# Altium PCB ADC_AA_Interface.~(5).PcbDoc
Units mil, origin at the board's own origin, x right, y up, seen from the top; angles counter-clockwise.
Board outline 2600 x 10000 mil, 6 copper layers (Top Layer, InternalPlane1, MidLayer1, InternalPlane2, InternalPlane3, Bottom Layer); 10 components, 66 nets, 255 pads, 1 vias.
Unrouted connection lines stored in the file: 32.
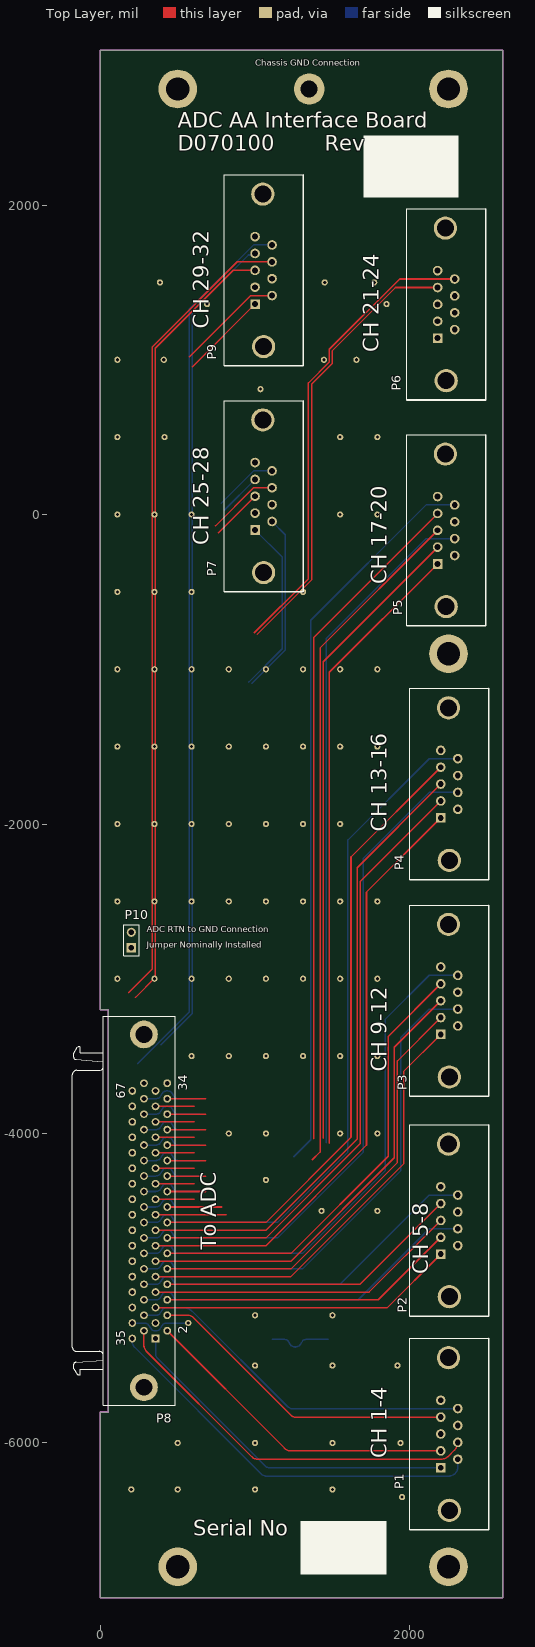
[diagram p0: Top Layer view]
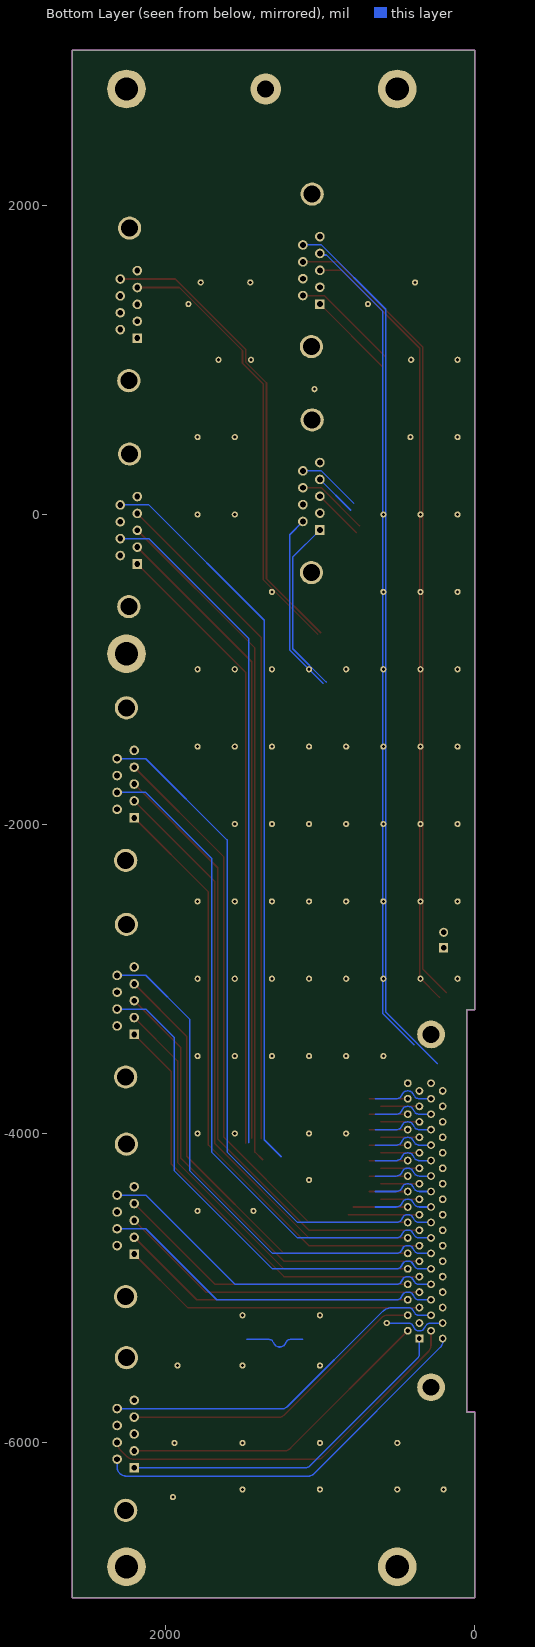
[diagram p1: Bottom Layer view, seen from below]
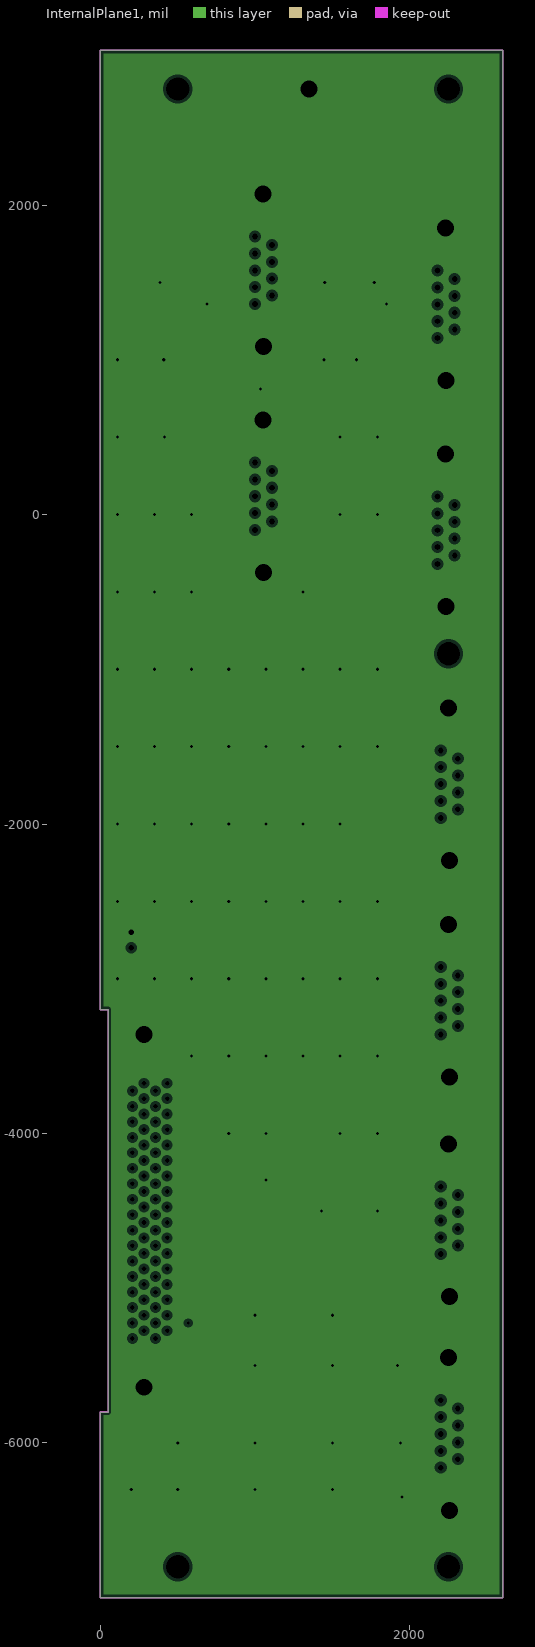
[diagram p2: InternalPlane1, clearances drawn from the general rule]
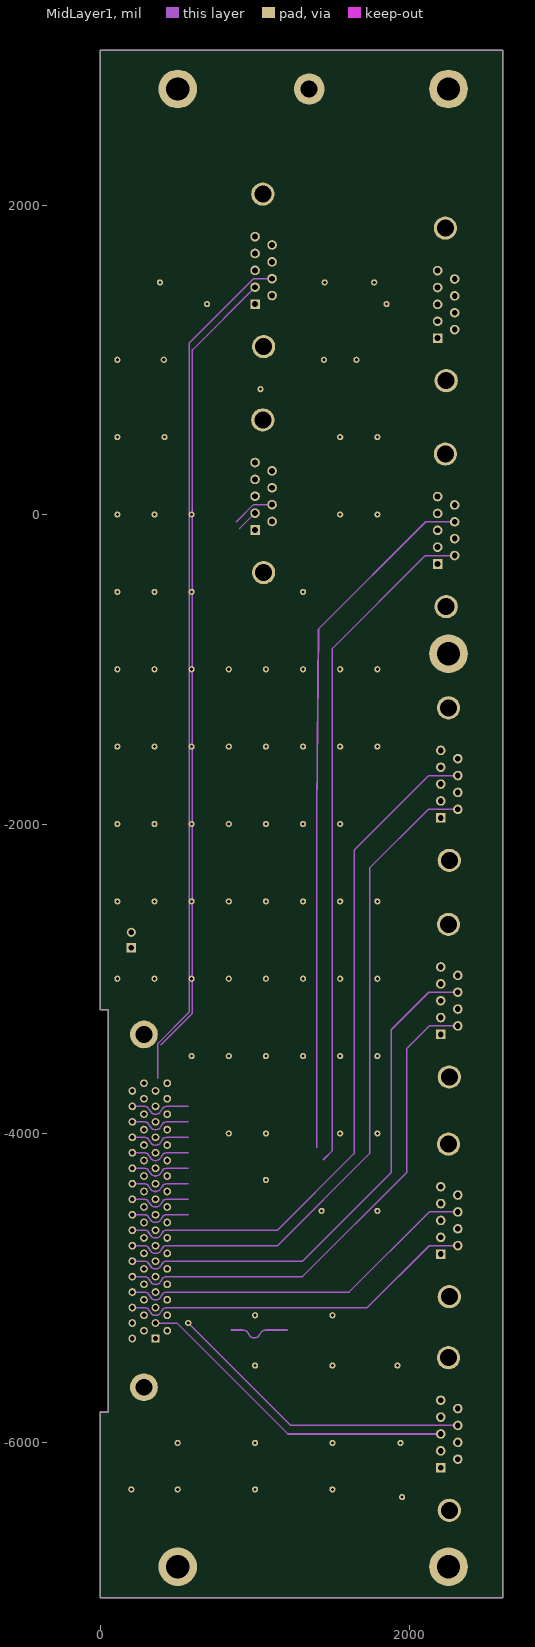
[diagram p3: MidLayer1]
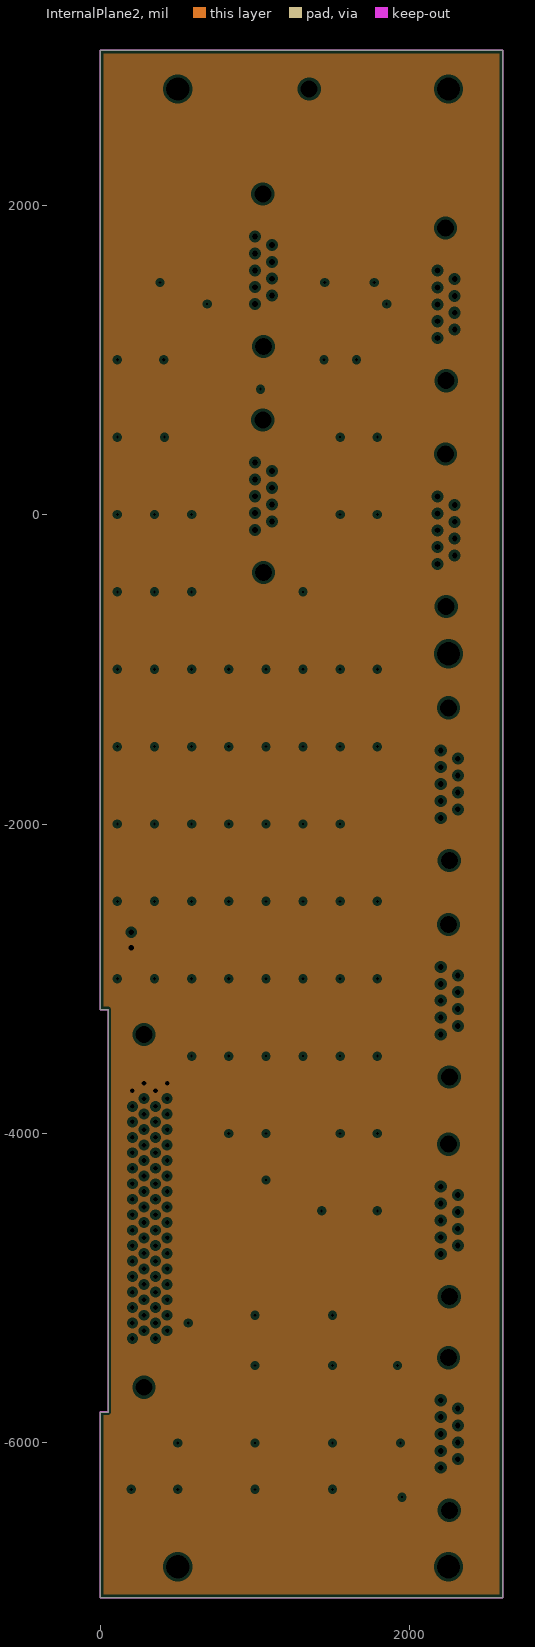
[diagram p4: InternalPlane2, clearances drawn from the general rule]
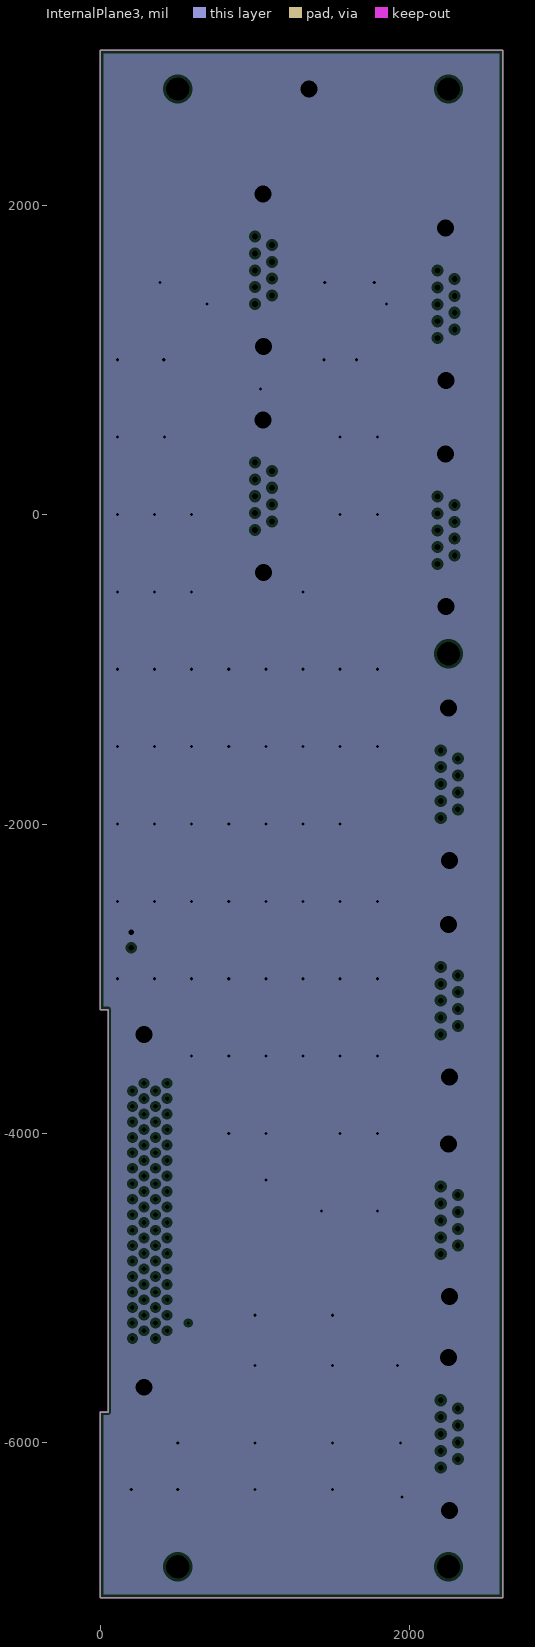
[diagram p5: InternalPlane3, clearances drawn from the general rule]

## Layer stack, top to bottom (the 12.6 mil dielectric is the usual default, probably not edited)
Top Solder: solder mask 0.4, Solder Resist, Dk 3.5
Top Layer: signal copper 1.4
Dielectric1: core 12.6, FR-4, Dk 4.8
InternalPlane1: plane copper 1.4, net GND
Dielectric3: prepreg 12.6, FR-4, Dk 4.8
MidLayer1: signal copper 1.4
Dielectric2: core 12.6, FR-4, Dk 4.8
InternalPlane2: plane copper 1.4, net RTN
Dielectric4: prepreg 12.6, FR-4, Dk 4.8
InternalPlane3: plane copper 1.4, net GND
Dielectric5: core 12.6, FR-4, Dk 4.8
Bottom Layer: signal copper 1.4
Bottom Solder: solder mask 0.4, Solder Resist, Dk 3.5

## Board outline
0,-7000 0,-5800 50,-5800 50,-3200 0,-3200 0,3000 2600,3000 2600,-7000

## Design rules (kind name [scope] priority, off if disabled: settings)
Clearance [All] p1: gap=10 ignorepadtopadclearanceinfootprint=FALSE except(0: Arc-Hole Track-Hole SMDPad-Hole THPad-Hole Via-Hole Fill-Hole Poly-Hole Region-Hole Text-Hole)
FabricationTestPointUsage TestPointUsage [All] p1: valid=0 allowmultiple=FALSE
FabricationTestpoint Testpoint [All] p1: side=3 testpointundercomponent=TRUE minsize=40 maxsize=100 preferedsize=60 minholesize=0 maxholesize=40 preferedholesize=32 testpointgrid=1 allowsidetop=TRUE allowsidebottom=TRUE usegrid=TRUE gridtolerance=0.01
HoleSize [All] p1: absolutevalues=TRUE maxlimit=200 minlimit=1 maxpercent=80.000 minpercent=20.000
PlaneClearance [All] p1: clearance=20
PlaneConnect [All] p1: planeconnectstyle=Relief reliefexpansion=20 reliefentries=4 reliefconductorwidth=10 reliefairgap=10
PolygonConnect [All] p1: connectstyle=Relief reliefconductorwidth=10 reliefentries=4 polygonreliefangle="90 Angle" airgapwidth=10
RoutingVias [All] p1: holewidth=20 width=40 viastyle="Through Hole" minholewidth=20 minwidth=40 maxholewidth=28 maxwidth=50
SolderMaskExpansion [All] p1: expansion=4
Width [All] p1: maxlimit=100 minlimit=10 preferedwidth=10
25 further rules are at their usual default settings.

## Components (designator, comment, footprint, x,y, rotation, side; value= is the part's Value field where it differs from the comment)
P1 "5747871-8" DB9/M 2200,-6160 r270 top
P2 "5747871-8" DB9/M 2200,-4780 r270 top
P3 "5747871-8" DB9/M 2200,-3360 r270 top
P4 "5747871-8" DB9/M 2200,-1960 r270 top
P5 "5747871-8" DB9/M 2180,-320 r270 top
P6 "5747871-8" DB9/M 2180,1140 r270 top
P7 "5747871-8" DB9/M 1000,-100 r270 top
P8 "787082-7" 787082-7 20,-4500 r90 top
P9 "5747871-8" DB9/M 1000,1360 r270 top
P10 "Header 2" HDR1X2 200,-2800 r90 top

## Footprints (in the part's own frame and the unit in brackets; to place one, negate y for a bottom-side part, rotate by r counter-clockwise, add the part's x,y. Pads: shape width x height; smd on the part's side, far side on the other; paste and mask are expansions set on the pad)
787082-7 [mm] "Connector; D Subminiature 050 Series; 68 Position; Right Angle"
  rect 1.27x1.27 hole 0.762: 1(-20.955,-8.555)
  round 1.27 hole 0.762: 2(-19.685,-10.46) 3(-18.415,-8.555) 4(-17.145,-10.46) 5(-15.875,-8.555) 6(-14.605,-10.46) 7(-13.335,-8.555) 8(-12.065,-10.46) 9(-10.795,-8.555) 10(-9.525,-10.46) 11(-8.255,-8.555) 12(-6.985,-10.46) 13(-5.715,-8.555) 14(-4.445,-10.46) 15(-3.175,-8.555) 16(-1.905,-10.46) 17(-0.635,-8.555) 18(0.635,-10.46) 19(1.905,-8.555) 20(3.175,-10.46) 21(4.445,-8.555) 22(5.715,-10.46) 23(6.985,-8.555) 24(8.255,-10.46) 25(9.525,-8.555) 26(10.795,-10.46) 27(12.065,-8.555) 28(13.335,-10.46) 29(14.605,-8.555) 30(15.875,-10.46) 31(17.145,-8.555) 32(18.415,-10.46) 33(19.685,-8.555) 34(20.955,-10.46) 35(-20.955,-4.745) 36(-19.685,-6.65) 37(-18.415,-4.745) 38(-17.145,-6.65) 39(-15.875,-4.745) 40(-14.605,-6.65) 41(-13.335,-4.745) 42(-12.065,-6.65) 43(-10.795,-4.745) 44(-9.525,-6.65) 45(-8.255,-4.745) 46(-6.985,-6.65) 47(-5.715,-4.745) 48(-4.445,-6.65) 49(-3.175,-4.745) 50(-1.905,-6.65) 51(-0.635,-4.745) 52(0.635,-6.65) 53(1.905,-4.745) 54(3.175,-6.65) 55(4.445,-4.745) 56(5.715,-6.65) 57(6.985,-4.745) 58(8.255,-6.65) 59(9.525,-4.745) 60(10.795,-6.65) 61(12.065,-4.745) 62(13.335,-6.65) 63(14.605,-4.745) 64(15.875,-6.65) 65(17.145,-4.745) 66(18.415,-6.65) 67(19.685,-4.745) 68(20.955,-6.65)
  round 4.55 hole 2.77: 69(-28.955,-6.65) 70(28.955,-6.65)
  silkscreen extent -31.95,-11.76 31.95,5.11
DB9/M [mil]
  round 150 hole 110: 0(-711,50) 0(275,55)
  rect 62x62 hole 38: 1(0,0)
  round 62 hole 38: 2(-109,0) 3(-218,0) 4(-327,0) 5(-436,0) 6(-55,110) 7(-164,110) 8(-273,110) 9(-382,110)
  silkscreen extent -836,-200 400,310
HDR1X2 [mm] "Connector; Header; 2 Position"
  rect 1.5x1.5 hole 0.9: 1(0,0)
  round 1.5 hole 0.9: 2(2.54,0)
  silkscreen extent -1.27,-1.27 3.81,1.27

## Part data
P1 P2 P3 P4 P5 P6 P7 P9: library part 788754-1, "Plug Assembly, Size 1, 9 Position, Right Angle, 8.08mm Series, Amplimite"
P8: library part "PE50E-080 Connector", "3M Pak 50 plug connector"
P10: "Header, 2-Pin"

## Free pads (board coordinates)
  round 40 hole 20: 0(500,-6000) 1(1000,-6000) 2(1500,-6000) 3(1940,-6000) 4(1000,-5500) 5(1500,-5500) 6(1920,-5500) 9(1790,-4500) 10(1000,-5175) 11(1500,-5175) 16(1790,-4000) 17(1790,-3500) 20(1070,-4300) 20(1430,-4500) 22(1550,-4000) 23(1550,-3500) 24(1550,-3000) 31(1310,-3000) 32(1310,-3500) 33(1790,-3000) 37(830,-4000) 38(830,-3500) 39(830,-3000) 40(830,-2500) 41(350,-2500) 42(590,-2500) 43(350,-3000) 44(590,-3000) 45(1070,-2500) 46(1790,-2500) 47(1310,-2500) 48(1550,-2500) 50(590,-3500) 52(1070,-4000) 53(1070,-3500) 54(1070,-3000) 55(350,-2000) 56(590,-2000) 57(830,-2000) 58(1070,-2000) 60(1310,-2000) 61(1550,-2000) 62(1550,-1500) 63(1310,-1500) 64(1790,-1500) 64(1790,-1000) 65(1070,-1500) 66(830,-1500) 67(590,-1500) 68(350,-1500) 69(350,-1000) 70(590,-1000) 71(830,-1000) 72(1070,-1000) 73(1310,-1000) 74(1550,-1000) 76(110,1000) 77(110,500) 78(110,0) 78(350,-500) 79(110,-500) 79(590,-500) 80(110,-1000) 81(110,-1500) 82(110,-2000) 82(1310,-500) 83(110,-2500) 83(350,0) 84(110,-3000) 84(590,0) 85(200,-6300) 85(1790,0) 86(500,-6300) 86(1550,0) 87(1000,-6300) 87(1550,500) 88(415,500) 88(1500,-6300) 89(410,1000) 89(1950,-6350) 90(1035,810) 91(1445,1000) 92(1655,1000) 93(1790,500) 94(1450,1500) 95(1770,1500) 96(385,1500) 97(690,1360) 98(1850,1360)
  round 200 hole 110: 0(1350,2750)
  round 250 hole 150: 0(2250,-6800) 1(2250,2750) 2(500,2750) 3(500,-6800) 4(2250,-900)

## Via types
v1: diameter 40, hole 20, Top Layer to Bottom Layer, 1 vias

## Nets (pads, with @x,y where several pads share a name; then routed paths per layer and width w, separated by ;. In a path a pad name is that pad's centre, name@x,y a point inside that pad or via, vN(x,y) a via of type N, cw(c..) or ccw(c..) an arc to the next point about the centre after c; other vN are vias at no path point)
GND: P1.0 P2.0 P3.0 P4.0 P5.0 P6.0 P7.0 P8.69 P8.70 P9.0 P10.2 pad.0@500,-6000 pad.0@1350,2750 pad.1@1000,-6000 pad.2@1500,-6000 pad.3@1940,-6000 pad.4@1000,-5500 pad.5 pad.6 pad.9 pad.10 pad.11 pad.16 pad.17 pad.20 pad.22 pad.23 pad.24 pad.31 pad.32 pad.33 pad.37 pad.38 pad.39 pad.40 pad.41 pad.42 pad.43 pad.44 pad.45 pad.46 pad.47 pad.48 pad.50 pad.52 pad.53 pad.54 pad.55 pad.56 pad.57 pad.58 pad.60 pad.61 pad.62 pad.63 pad.64 pad.65 pad.66 pad.67 pad.68 pad.69 pad.70 pad.71 pad.72 pad.73 pad.74 pad.76 pad.77 pad.78 pad.79 pad.80 pad.81 pad.82 pad.83 pad.84 pad.85 pad.86 pad.87 pad.88 pad.89 pad.90 pad.91 pad.92 pad.93 pad.94 pad.95 pad.96 pad.97 pad.98
OUTPUTN1: P1.6 P8.35 | length 2576
  Bottom Layer w10: P8.35 206.81,-5348.16 ccw(c251.84,-5348.16) 220,-5380 1040,-6200 ccw(c1073.8,-6166.2) 1073.8,-6214 2251.92,-6214 ccw(c2251.92,-6155.87) 2293.03,-6196.97 ccw(c2251.96,-6155.96) 2310,-6155.96 P1.6
OUTPUTN2: P1.7 P8.36 | length 2523.7
  Top Layer w10: P8.36 281.81,-5370 ccw(c334.47,-5370) 297.23,-5407.23 ; 300,-5410 297.23,-5407.23 ; 1020,-6105 1016.21,-6105 ; P1.7@2310,-6020 P1.7 cw(c2239.99,-5996) 2289.49,-6045.51 2251.21,-6083.79 cw(c2200,-6032.57) 2200,-6105 1016.21,-6105 ; 297.23,-5407.23 980.03,-6090.03 ccw(c1016.21,-6053.79) 1016.21,-6105
OUTPUTN3: P1.8 P8.37 | length 2419.6
  MidLayer1 w10: v1(568.12,-5225) 1230.12,-5887 P1.8
  Bottom Layer w10: P8.37 280,-5225 ; 281.81,-5225 cw(c281.81,-5275) 307.3,-5231.99 ; 406.18,-5232.07 382.54,-5267.87 cw(c356.81,-5225) 331.08,-5267.87 307.44,-5232.07 ; 406.32,-5231.99 cw(c431.81,-5275) 431.81,-5225 v1(568.12,-5225) ; 307.3,-5231.99 cw(c281.81,-5275) 307.44,-5232.07 ; 307.3,-5231.99 cw(c356.81,-5225) 307.28,-5231.82 307.44,-5232.07
OUTPUTN4: P1.9 P8.38 | length 2322.5
  Bottom Layer w10: P8.38 355,-5175 ; 356.81,-5175 ccw(c356.81,-5125) 382.3,-5168.01 ; 382.44,-5167.93 406.08,-5132.13 cw(c431.81,-5175) 431.81,-5125 528.58,-5125 cw(c528.58,-5225) 599.29,-5154.29 1210.98,-5765.98 ccw(c1240,-5736.96) 1240,-5778 ; 1230,-5778 1240,-5778 ; P1.9 1240,-5778
OUTPUTN5: P2.6 P8.39 | length 2311
  MidLayer1 w10: P8.39 280,-5125 ; 281.81,-5125 cw(c281.81,-5175) 307.3,-5131.99 ; 406.18,-5132.07 382.54,-5167.87 cw(c356.81,-5125) 356.81,-5175 cw(c356.81,-5125) 331.08,-5167.87 307.44,-5132.07 ; 406.32,-5131.99 cw(c431.81,-5175) 431.81,-5125 1725,-5125 2125,-4725 P2.6 ; 307.3,-5131.99 cw(c356.81,-5125) 307.28,-5131.82 307.44,-5132.07 ; 307.3,-5131.99 cw(c281.81,-5175) 307.44,-5132.07
OUTPUTN6: P2.7 P8.40 | length 2260.5
  Bottom Layer w10: P8.40 355,-5075 ; 356.81,-5075 ccw(c356.81,-5025) 382.3,-5068.01 ; 481.18,-5067.93 457.54,-5032.13 ccw(c431.81,-5075) 431.81,-5025 ccw(c431.81,-5075) 406.08,-5032.13 382.44,-5067.93 ; 481.32,-5068.01 ccw(c506.81,-5025) 506.81,-5075 1666,-5075 2125,-4616 P2.7 ; 382.3,-5068.01 ccw(c356.81,-5025) 382.44,-5067.93 ; 382.3,-5068.01 ccw(c431.81,-5075) 382.28,-5068.18 382.44,-5067.93
OUTPUTN7: P2.8 P8.41 | length 2359.9
  MidLayer1 w10: P8.41 280,-5025 ; 281.81,-5025 cw(c281.81,-5075) 307.3,-5031.99 ; 406.18,-5032.07 382.54,-5067.87 cw(c356.81,-5025) 356.81,-5075 cw(c356.81,-5025) 331.08,-5067.87 307.44,-5032.07 ; 406.32,-5031.99 cw(c431.81,-5075) 431.81,-5025 1607,-5025 2125,-4507 P2.8 ; 307.3,-5031.99 cw(c356.81,-5025) 307.28,-5031.82 307.44,-5032.07 ; 307.3,-5031.99 cw(c281.81,-5075) 307.44,-5032.07
OUTPUTN8: P2.9 P8.42 | length 2309.4
  Bottom Layer w10: P8.42 355,-4975 ; 356.81,-4975 ccw(c356.81,-4925) 382.3,-4968.01 ; 481.18,-4967.93 457.54,-4932.13 ccw(c431.81,-4975) 406.08,-4932.13 382.44,-4967.93 ; 481.32,-4968.01 ccw(c506.81,-4925) 506.81,-4975 1548,-4975 2125,-4398 P2.9 ; 382.3,-4968.01 ccw(c431.81,-4975) 382.28,-4968.18 382.44,-4967.93 ; 382.3,-4968.01 ccw(c356.81,-4925) 382.44,-4967.93
OUTPUTN9: P3.6 P8.43 | length 3286.1
  MidLayer1 w10: P8.43 280,-4925 ; 281.81,-4925 cw(c281.81,-4975) 307.3,-4931.99 ; 406.18,-4932.07 382.54,-4967.87 cw(c356.81,-4925) 356.81,-4975 cw(c356.81,-4925) 331.08,-4967.87 307.44,-4932.07 ; 406.32,-4931.99 cw(c431.81,-4975) 431.81,-4925 1306.81,-4925 1980,-4251.81 1980,-3450 2125,-3305 P3.6 ; 307.3,-4931.99 cw(c356.81,-4925) 307.28,-4931.82 307.44,-4932.07 ; 307.3,-4931.99 cw(c281.81,-4975) 307.44,-4932.07
OUTPUTN10: P3.7 P8.44 | length 3270.1
  Bottom Layer w10: P8.44 355,-4875 ; 356.81,-4875 ccw(c356.81,-4825) 382.3,-4868.01 ; 481.18,-4867.93 457.54,-4832.13 ccw(c431.81,-4875) 431.81,-4825 ccw(c431.81,-4875) 406.08,-4832.13 382.44,-4867.93 ; 481.32,-4868.01 ccw(c506.81,-4825) 506.81,-4875 1306.81,-4875 1940,-4241.81 1940,-3381 2125,-3196 P3.7 ; 382.3,-4868.01 ccw(c356.81,-4825) 382.44,-4867.93 ; 382.3,-4868.01 ccw(c431.81,-4875) 382.28,-4868.18 382.44,-4867.93
OUTPUTN11: P3.8 P8.45 | length 3405.2
  MidLayer1 w10: P8.45 280,-4825 ; 281.81,-4825 cw(c281.81,-4875) 307.3,-4831.99 ; 406.18,-4832.07 382.54,-4867.87 cw(c356.81,-4825) 356.81,-4875 cw(c356.81,-4825) 331.08,-4867.87 307.44,-4832.07 ; 406.32,-4831.99 cw(c431.81,-4875) 431.81,-4825 1306.81,-4825 1880,-4251.81 1880,-3330 2123,-3087 P3.8 ; 307.3,-4831.99 cw(c356.81,-4825) 307.28,-4831.82 307.44,-4832.07 ; 307.3,-4831.99 cw(c281.81,-4875) 307.44,-4832.07
OUTPUTN12: P3.9 P8.46 | length 3388.1
  Bottom Layer w10: P8.46 355,-4775 ; 356.81,-4775 ccw(c356.81,-4725) 382.3,-4768.01 ; 481.18,-4767.93 457.54,-4732.13 ccw(c431.81,-4775) 431.81,-4725 ccw(c431.81,-4775) 406.08,-4732.13 382.44,-4767.93 ; 481.32,-4768.01 ccw(c506.81,-4725) 506.81,-4775 1306.81,-4775 1840,-4241.81 1840,-3263 2125,-2978 P3.9 ; 382.3,-4768.01 ccw(c356.81,-4725) 382.44,-4767.93 ; 382.3,-4768.01 ccw(c431.81,-4775) 382.28,-4768.18 382.44,-4767.93
OUTPUTN13: P4.6 P8.47 | length 5232.7
  MidLayer1 w10: P8.47 280,-4725 ; 281.81,-4725 cw(c281.81,-4775) 307.3,-4731.99 ; 406.18,-4732.07 382.54,-4767.87 cw(c356.81,-4725) 356.81,-4775 cw(c356.81,-4725) 331.08,-4767.87 307.44,-4732.07 ; 406.32,-4731.99 cw(c431.81,-4775) 431.81,-4725 1145,-4725 ; 2120,-1905 1740,-2285 1740,-4130 ; 2123,-1905 P4.6 ; 307.3,-4731.99 cw(c356.81,-4725) 307.28,-4731.82 307.44,-4732.07 ; 307.3,-4731.99 cw(c281.81,-4775) 307.44,-4732.07 ; 1145,-4725 1740,-4130 ; 1145,-4725 1740,-4130
OUTPUTN14: P4.7 P8.48 | length 4375.3
  Bottom Layer w10: P8.48 355,-4675 ; 356.81,-4675 ccw(c356.81,-4625) 382.3,-4668.01 ; 481.18,-4667.93 457.54,-4632.13 ccw(c431.81,-4675) 431.81,-4625 ccw(c431.81,-4675) 406.08,-4632.13 382.44,-4667.93 ; 481.32,-4668.01 ccw(c506.81,-4625) 506.81,-4675 1145,-4675 1700,-4120 1700,-2221 2125,-1796 P4.7 ; 382.3,-4668.01 ccw(c356.81,-4625) 382.44,-4667.93 ; 382.3,-4668.01 ccw(c431.81,-4675) 382.28,-4668.18 382.44,-4667.93
OUTPUTN15: P4.8 P8.49 | length 4510.5
  MidLayer1 w10: P8.49 280,-4625 ; 281.81,-4625 cw(c281.81,-4675) 307.3,-4631.99 ; 406.18,-4632.07 382.54,-4667.87 cw(c356.81,-4625) 356.81,-4675 cw(c356.81,-4625) 331.08,-4667.87 307.44,-4632.07 ; 406.32,-4631.99 cw(c431.81,-4675) 431.81,-4625 1145,-4625 1640,-4130 1640,-2170 2123,-1687 P4.8 ; 307.3,-4631.99 cw(c356.81,-4625) 307.28,-4631.82 307.44,-4632.07 ; 307.3,-4631.99 cw(c281.81,-4675) 307.44,-4632.07
OUTPUTN16: P4.9 P8.50 | length 4493.3
  Bottom Layer w10: P8.50 355,-4575 ; 356.81,-4575 ccw(c356.81,-4525) 382.3,-4568.01 ; 481.18,-4567.93 457.54,-4532.13 ccw(c431.81,-4575) 431.81,-4525 ccw(c431.81,-4575) 406.08,-4532.13 382.44,-4567.93 ; 481.32,-4568.01 ccw(c506.81,-4525) 506.81,-4575 1145,-4575 1600,-4120 1600,-2103 2125,-1578 P4.9 ; 382.3,-4568.01 ccw(c356.81,-4525) 382.44,-4567.93 ; 382.3,-4568.01 ccw(c431.81,-4575) 382.28,-4568.18 382.44,-4567.93
OUTPUTN17: P5.6 P8.51 | length 4768.9
  MidLayer1 w10: P8.51 280,-4525 ; 281.81,-4525 cw(c281.81,-4575) 307.3,-4531.99 ; 406.18,-4532.07 382.54,-4567.87 cw(c356.81,-4525) 356.81,-4575 cw(c356.81,-4525) 331.08,-4567.87 307.44,-4532.07 ; 406.32,-4531.99 cw(c431.81,-4575) 431.81,-4525 568.12,-4525 ; 1440,-4170 1500,-4110 1500,-865 2100,-265 ; 2103,-265 P5.6 ; 307.3,-4531.99 cw(c356.81,-4525) 307.28,-4531.82 307.44,-4532.07 ; 307.3,-4531.99 cw(c281.81,-4575) 307.44,-4532.07
OUTPUTN18: P5.7 P8.52 | length 4759.6
  Bottom Layer w10: P8.52 355,-4475 ; 356.81,-4475 ccw(c356.81,-4425) 382.3,-4468.01 ; 481.18,-4467.93 457.54,-4432.13 ccw(c431.81,-4475) 431.81,-4425 ccw(c431.81,-4475) 406.08,-4432.13 382.44,-4467.93 ; 481.32,-4468.01 ccw(c506.81,-4425) 506.81,-4475 643.12,-4475 ; 1460,-4060 1460,-801 2105,-156 P5.7 ; 382.3,-4468.01 ccw(c356.81,-4425) 382.44,-4467.93 ; 382.3,-4468.01 ccw(c431.81,-4475) 382.28,-4468.18 382.44,-4467.93
OUTPUTN19: P5.8 P8.53 | length 4922.2
  MidLayer1 w10: P8.53 280,-4425 ; 281.81,-4425 cw(c281.81,-4475) 307.3,-4431.99 ; 406.18,-4432.07 382.54,-4467.87 cw(c356.81,-4425) 356.81,-4475 cw(c356.81,-4425) 331.08,-4467.87 307.44,-4432.07 ; 406.32,-4431.99 cw(c431.81,-4475) 431.81,-4425 568.12,-4425 ; 1400,-4091.63 1400,-1932.13 1410,-740 2103,-47 P5.8 ; 307.3,-4431.99 cw(c356.81,-4425) 307.28,-4431.82 307.44,-4432.07 ; 307.3,-4431.99 cw(c281.81,-4475) 307.44,-4432.07
OUTPUTN20: P5.9 P8.54 | length 5154.6
  Bottom Layer w10: P8.54 355,-4375 ; 356.81,-4375 ccw(c356.81,-4325) 382.3,-4368.01 ; 481.18,-4367.93 457.54,-4332.13 ccw(c431.81,-4375) 431.81,-4325 ccw(c431.81,-4375) 406.08,-4332.13 382.44,-4367.93 ; 481.32,-4368.01 ccw(c506.81,-4325) 506.81,-4375 643.12,-4375 ; 1250,-4150 1360,-4040 1360,-683 2105,62 P5.9 ; 382.3,-4368.01 ccw(c356.81,-4325) 382.44,-4367.93 ; 382.3,-4368.01 ccw(c431.81,-4375) 382.28,-4368.18 382.44,-4367.93
OUTPUTN21: P6.6 P8.55 | length 403.5
  MidLayer1 w10: P8.55 280,-4325 ; 281.81,-4325 cw(c281.81,-4375) 307.3,-4331.99 ; 406.18,-4332.07 382.54,-4367.87 cw(c356.81,-4325) 331.08,-4367.87 307.44,-4332.07 ; 406.32,-4331.99 cw(c431.81,-4375) 431.81,-4325 568.12,-4325 ; 307.3,-4331.99 cw(c356.81,-4325) 307.28,-4331.82 307.44,-4332.07 ; 307.3,-4331.99 cw(c281.81,-4375) 307.44,-4332.07
OUTPUTN22: P6.7 P8.56 | length 403.5
  Bottom Layer w10: P8.56 355,-4275 ; 356.81,-4275 ccw(c356.81,-4225) 382.3,-4268.01 ; 481.18,-4267.93 457.54,-4232.13 ccw(c431.81,-4275) 406.08,-4232.13 382.44,-4267.93 ; 481.32,-4268.01 ccw(c506.81,-4225) 506.81,-4275 643.12,-4275 ; 382.3,-4268.01 ccw(c356.81,-4225) 382.44,-4267.93 ; 382.3,-4268.01 ccw(c431.81,-4275) 382.28,-4268.18 382.44,-4267.93
OUTPUTN23: P6.8 P8.57 | length 403.5
  MidLayer1 w10: P8.57 280,-4225 ; 281.81,-4225 cw(c281.81,-4275) 307.3,-4231.99 ; 406.18,-4232.07 382.54,-4267.87 cw(c356.81,-4225) 331.08,-4267.87 307.44,-4232.07 ; 406.32,-4231.99 cw(c431.81,-4275) 431.81,-4225 568.12,-4225 ; 307.3,-4231.99 cw(c356.81,-4225) 307.28,-4231.82 307.44,-4232.07 ; 307.3,-4231.99 cw(c281.81,-4275) 307.44,-4232.07
OUTPUTN24: P6.9 P8.58 | length 3434.8
  Top Layer w10: 995,-764.5 1345,-414.5 1345,850.5 1480,985.5 1480,1067.78 1934.22,1522 P6.9
  Bottom Layer w10: P8.58 355,-4175 ; 356.81,-4175 ccw(c356.81,-4125) 382.3,-4168.01 ; 481.18,-4167.93 457.54,-4132.13 ccw(c431.81,-4175) 406.08,-4132.13 382.44,-4167.93 ; 481.32,-4168.01 ccw(c506.81,-4125) 506.81,-4175 643.12,-4175 ; 382.3,-4168.01 ccw(c356.81,-4125) 382.44,-4167.93 ; 382.3,-4168.01 ccw(c431.81,-4175) 382.28,-4168.18 382.44,-4167.93
OUTPUTN25: P7.6 P8.59 | length 1573.2
  MidLayer1 w10: P8.59 280,-4125 ; 281.81,-4125 cw(c281.81,-4175) 307.3,-4131.99 ; 406.18,-4132.07 382.54,-4167.87 cw(c356.81,-4125) 331.08,-4167.87 307.44,-4132.07 ; 406.32,-4131.99 cw(c431.81,-4175) 431.81,-4125 568.12,-4125 ; 307.3,-4131.99 cw(c356.81,-4125) 307.28,-4131.82 307.44,-4132.07 ; 307.3,-4131.99 cw(c281.81,-4175) 307.44,-4132.07
  Bottom Layer w10: 980,-1090.5 1195,-875.5 1195,-130 P7.6
OUTPUTN26: P7.7 P8.60 | length 679
  MidLayer1 w10: 880,-45.95 989.95,64 P7.7
  Bottom Layer w10: P8.60 355,-4075 ; 356.81,-4075 ccw(c356.81,-4025) 382.3,-4068.01 ; 481.18,-4067.93 457.54,-4032.13 ccw(c431.81,-4075) 406.08,-4032.13 382.44,-4067.93 ; 481.32,-4068.01 ccw(c506.81,-4025) 506.81,-4075 643.12,-4075 ; 382.3,-4068.01 ccw(c356.81,-4025) 382.44,-4067.93 ; 382.3,-4068.01 ccw(c431.81,-4075) 382.28,-4068.18 382.44,-4067.93
OUTPUTN27: P7.8 P8.61 | length 871.9
  Top Layer w10: 743.6,-73.35 989.95,173 P7.8
  MidLayer1 w10: P8.61 280,-4025 ; 281.81,-4025 cw(c281.81,-4075) 307.3,-4031.99 ; 406.18,-4032.07 382.54,-4067.87 cw(c356.81,-4025) 331.08,-4067.87 307.44,-4032.07 ; 406.32,-4031.99 cw(c431.81,-4075) 431.81,-4025 568.12,-4025 ; 307.3,-4031.99 cw(c356.81,-4025) 307.28,-4031.82 307.44,-4032.07 ; 307.3,-4031.99 cw(c281.81,-4075) 307.44,-4032.07
OUTPUTN28: P7.9 P8.62 | length 820.4
  Bottom Layer w10: P8.62 355,-3975 ; 356.81,-3975 ccw(c356.81,-3925) 382.3,-3968.01 ; 481.18,-3967.93 457.54,-3932.13 ccw(c431.81,-3975) 406.08,-3932.13 382.44,-3967.93 ; 481.32,-3968.01 ccw(c506.81,-3925) 506.81,-3975 643.12,-3975 ; 780,72.05 989.95,282 P7.9 ; 382.3,-3968.01 ccw(c356.81,-3925) 382.44,-3967.93 ; 382.3,-3968.01 ccw(c431.81,-3975) 382.28,-3968.18 382.44,-3967.93
OUTPUTN29: P8.63 P9.6 | length 1102.8
  Top Layer w10: 575,1018.21 971.79,1415 P9.6
  MidLayer1 w10: P8.63 280,-3925 ; 281.81,-3925 cw(c281.81,-3975) 307.3,-3931.99 ; 406.18,-3932.07 382.54,-3967.87 cw(c356.81,-3925) 331.08,-3967.87 307.44,-3932.07 ; 406.32,-3931.99 cw(c431.81,-3975) 431.81,-3925 568.12,-3925 ; 307.3,-3931.99 cw(c356.81,-3925) 307.28,-3931.82 307.44,-3932.07 ; 307.3,-3931.99 cw(c281.81,-3975) 307.44,-3932.07
OUTPUTN30: P8.64 P9.7 | length 5945.1
  MidLayer1 w10: 371.81,-3641.57 371.81,-3417.92 575,-3214.73 575,1109.05 989.95,1524 P9.7
  Bottom Layer w10: P8.64 355,-3875 ; 356.81,-3875 ccw(c356.81,-3825) 382.3,-3868.01 ; 481.18,-3867.93 457.54,-3832.13 ccw(c431.81,-3875) 406.08,-3832.13 382.44,-3867.93 ; 481.32,-3868.01 ccw(c506.81,-3825) 506.81,-3875 643.12,-3875 ; 382.3,-3868.01 ccw(c356.81,-3825) 382.44,-3867.93 ; 382.3,-3868.01 ccw(c431.81,-3875) 382.28,-3868.18 382.44,-3867.93
OUTPUTN31: P8.65 P9.8 | length 5641
  Top Layer w10: 182.97,-3088.84 335,-2936.81 335,1082.78 885.22,1633 P9.8
  MidLayer1 w10: P8.65 280,-3825 ; 281.81,-3825 cw(c281.81,-3875) 307.3,-3831.99 ; 406.18,-3832.07 382.54,-3867.87 cw(c356.81,-3825) 356.81,-3875 cw(c356.81,-3825) 331.08,-3867.87 307.44,-3832.07 ; 406.32,-3831.99 cw(c431.81,-3875) 431.81,-3825 568.12,-3825 ; 307.3,-3831.99 cw(c356.81,-3825) 307.28,-3831.82 307.44,-3832.07 ; 307.3,-3831.99 cw(c281.81,-3875) 307.44,-3832.07
OUTPUTN32: P8.66 P9.9 | length 6123.3
  Bottom Layer w10: 241.81,-3547.92 575,-3214.73 575,1327.05 989.95,1742 P9.9 ; P8.66 355,-3775 ; 356.81,-3775 ccw(c356.81,-3725) 382.3,-3768.01 ; 481.18,-3767.93 457.54,-3732.13 ccw(c431.81,-3775) 406.08,-3732.13 382.44,-3767.93 ; 481.32,-3768.01 ccw(c506.81,-3725) 506.81,-3775 643.12,-3775 ; 382.3,-3768.01 ccw(c356.81,-3725) 382.44,-3767.93 ; 382.3,-3768.01 ccw(c431.81,-3775) 382.28,-3768.18 382.44,-3767.93
OUTPUTP1: P1.1 P8.1 | length 2253.2
  Bottom Layer w10: P8.1 356.81,-5420 356.81,-5421.44 ccw(c401.84,-5421.44) 370,-5453.28 1066.72,-6150 1067.32,-6150.61 ; 1067.33,-6150.61 ccw(c1090,-6127.93) 1090,-6160 P1.1
OUTPUTP2: P1.2 P8.2 | length 2087.3
  Top Layer w10: P8.2 1190,-6033.19 1192.12,-6035.31 ccw(c1230,-5997.43) 1230,-6051 P1.2
OUTPUTP3: P1.3 P8.3 | length 2140.2
  MidLayer1 w10: P8.3 495,-5225 1212,-5942 P1.3
OUTPUTP4: P1.4 P8.4 | length 2037.2
  Top Layer w10: P8.4 567.62,-5175 cw(c567.62,-5221.51) 600.51,-5188.62 1234.19,-5822.31 ccw(c1260,-5796.5) 1260,-5833 P1.4
OUTPUTP5: P2.1 P8.5 | length 1986.1
  Top Layer w10: P8.5 1855,-5125 P2.1
OUTPUTP6: P2.2 P8.6 | length 1935.5
  Top Layer w10: P8.6 1796,-5075 P2.2
OUTPUTP7: P2.3 P8.7 | length 2035
  Top Layer w10: P8.7 1737,-5025 P2.3
OUTPUTP8: P2.4 P8.8 | length 1984.4
  Top Layer w10: P8.8 1678,-4975 P2.4
OUTPUTP9: P3.1 P8.9 | length 2841
  Top Layer w10: P8.9 1231.81,-4925 1960,-4196.81 1960,-3600 P3.1
OUTPUTP10: P3.2 P8.10 | length 2825
  Top Layer w10: P8.10 1231.81,-4875 1920,-4186.81 1920,-3531 P3.2
OUTPUTP11: P3.3 P8.11 | length 2959
  Top Layer w10: P8.11 1231.81,-4825 1900,-4156.81 1900,-3442 P3.3
OUTPUTP12: P3.4 P8.12 | length 2956
  Top Layer w10: P8.12 1231.81,-4775 1860,-4146.81 1860,-3373 P3.4 P3.4@2187,-3033
OUTPUTP13: P4.1 P8.13 | length 3946.3
  Top Layer w10: P8.13 1070,-4725 1720,-4075 1720,-2440 P4.1
OUTPUTP14: P4.2 P8.14 | length 3930.3
  Top Layer w10: P8.14 1070,-4675 1680,-4065 1680,-2371 P4.2
OUTPUTP15: P4.3 P8.15 | length 4064.3
  Top Layer w10: P8.15 1070,-4625 1660,-4035 1660,-2282 P4.3
OUTPUTP16: P4.4 P8.16 | length 4048.3
  Top Layer w10: P8.16 1070,-4575 1620,-4025 1620,-2213 P4.4
OUTPUTP17: P5.1 P8.17 | length 4490.3
  Top Layer w10: P8.17 815,-4525 ; 1480,-4062.13 1480,-1020 P5.1
OUTPUTP18: P5.2 P8.18 | length 4479.1
  Top Layer w10: P8.18 785,-4475 ; 1440,-4030.41 1440,-951 P5.2
OUTPUTP19: P5.3 P8.19 | length 4653.5
  Top Layer w10: P8.19 606.81,-4425 ; 1370,-4170 1420,-4120 1420,-862 P5.3
OUTPUTP20: P5.4 P8.20 | length 4622.2
  Top Layer w10: P8.20 681.81,-4375 ; 1380,-4033.85 1380,-793 P5.4
OUTPUTP21: P6.1 P8.21 | length 250
  Top Layer w10: P8.21 606.81,-4325
OUTPUTP22: P6.2 P8.22 | length 250
  Top Layer w10: P8.22 681.81,-4275
OUTPUTP23: P6.3 P8.23 | length 250
  Top Layer w10: P8.23 606.81,-4225
OUTPUTP24: P6.4 P8.24 | length 3132
  Top Layer w10: P8.24 681.81,-4175 ; 1015,-772.78 1365,-422.78 1365,842.22 1500,977.22 1500,1059.5 1907.5,1467 P6.4
OUTPUTP25: P7.1 P8.25 | length 1393.8
  Top Layer w10: P8.25 606.81,-4125
  Bottom Layer w10: 960,-1082.22 1175,-867.22 1175,-275 P7.1
OUTPUTP26: P7.2 P8.26 | length 391.4
  Top Layer w10: P8.26 681.81,-4075
  MidLayer1 w10: 900,-91 P7.2
OUTPUTP27: P7.3 P8.27 | length 584.3
  Top Layer w10: P8.27 606.81,-4025 ; 763.6,-118.4 P7.3
OUTPUTP28: P7.4 P8.28 | length 532.8
  Top Layer w10: P8.28 681.81,-3975
  Bottom Layer w10: 800,27 P7.4
OUTPUTP29: P8.29 P9.1 | length 822.8
  Top Layer w10: P8.29 606.81,-3925 ; 595,955 P9.1
OUTPUTP30: P8.30 P9.2 | length 5397.1
  Top Layer w10: P8.30 681.81,-3875
  MidLayer1 w10: 391.81,-3426.2 595,-3223.01 595,1064 P9.2
OUTPUTP31: P8.31 P9.3 | length 5352
  Top Layer w10: 226.56,-3120.72 355,-2992.28 355,1074.5 858.5,1578 P9.3 ; P8.31 606.81,-3825
OUTPUTP32: P8.32 P9.4 | length 5634.2
  Top Layer w10: P8.32 681.81,-3775
  Bottom Layer w10: 391.81,-3426.2 595,-3223.01 595,1314.5 957.55,1677.05 990.05,1677.05 P9.4
RTN: P8.33 P8.34 P8.67 P8.68 P10.1
pads on no net: P1.5 P2.5 P3.5 P4.5 P5.5 P6.5 P7.5 P9.5
copper on no net: | length 806.9
  MidLayer1 w10: 845,-5270 918.19,-5270 ; 920,-5270 cw(c920,-5320) 945.49,-5276.99 ; 1044.37,-5277.07 1020.73,-5312.87 cw(c995,-5270) 969.27,-5312.87 945.63,-5277.07 ; 1044.51,-5276.99 cw(c1070,-5320) 1070,-5270 1206.31,-5270 ; 945.49,-5276.99 cw(c920,-5320) 945.63,-5277.07 ; 945.49,-5276.99 cw(c995,-5270) 945.47,-5276.82 945.63,-5277.07
  Bottom Layer w10: 1110,-5330 1183.19,-5330 ; 1185,-5330 cw(c1185,-5380) 1210.49,-5336.99 ; 1309.37,-5337.07 1285.73,-5372.87 cw(c1260,-5330) 1234.27,-5372.87 1210.63,-5337.07 ; 1309.51,-5336.99 cw(c1335,-5380) 1335,-5330 1471.31,-5330 ; 1210.49,-5336.99 cw(c1260,-5330) 1210.47,-5336.82 1210.63,-5337.07 ; 1210.49,-5336.99 cw(c1185,-5380) 1210.63,-5337.07

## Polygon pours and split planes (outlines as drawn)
GND on InternalPlane1 (split plane): 2579.9,-6979.9 20.1,-6979.9 20.1,-5820.1 50,-5820.1 53.92,-5819.71 57.69,-5818.57 61.17,-5816.71 64.21,-5814.21 66.71,-5811.17 68.57,-5807.69 69.71,-5803.92 70.1,-5800 70.1,-3200 69.71,-3196.08 68.57,-3192.31 66.71,-3188.83 64.21,-3185.79 61.17,-3183.29 57.69,-3181.43 53.92,-3180.29 50,-3179.9 20.1,-3179.9 20.1,2979.9 2579.9,2979.9
RTN on InternalPlane2 (split plane): 2579.9,-6979.9 20.1,-6979.9 20.1,-5820.1 50,-5820.1 53.92,-5819.71 57.69,-5818.57 61.17,-5816.71 64.21,-5814.21 66.71,-5811.17 68.57,-5807.69 69.71,-5803.92 70.1,-5800 70.1,-3200 69.71,-3196.08 68.57,-3192.31 66.71,-3188.83 64.21,-3185.79 61.17,-3183.29 57.69,-3181.43 53.92,-3180.29 50,-3179.9 20.1,-3179.9 20.1,2979.9 2579.9,2979.9
GND on InternalPlane3 (split plane): 2579.9,-6979.9 20.1,-6979.9 20.1,-5820.1 50,-5820.1 53.92,-5819.71 57.69,-5818.57 61.17,-5816.71 64.21,-5814.21 66.71,-5811.17 68.57,-5807.69 69.71,-5803.92 70.1,-5800 70.1,-3200 69.71,-3196.08 68.57,-3192.31 66.71,-3188.83 64.21,-3185.79 61.17,-3183.29 57.69,-3181.43 53.92,-3180.29 50,-3179.9 20.1,-3179.9 20.1,2979.9 2579.9,2979.9

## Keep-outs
Keep-Out Layer:
  the board outline again, w10

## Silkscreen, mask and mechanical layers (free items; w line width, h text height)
Top Overlay:
  rectangle: 1295,-6850 1850,-6505
  rectangle: 1700,2050 2315,2450
  text "Chassis GND Connection" at 1000,2900 h40
  text "ADC AA Interface Board" at 500,2500 h100
  text "D070100" at 500,2350 h100
  text "Rev" at 1450,2350 h100
  text "CH 29-32" at 700,1200 h100 r90
  text "CH 21-24" at 1800,1050 h100 r90
  text "CH 25-28" at 700,-200 h100 r90
  text "CH 17-20" at 1850,-450 h100 r90
  text "CH 13-16" at 1850,-2050 h100 r90
  text "ADC RTN to GND Connection" at 300,-2700 h40
  text "Jumper Nominally Installed" at 300,-2800 h40
  text "CH 9-12" at 1850,-3600 h100 r90
  text "To ADC" at 750,-4750 h100 r90
  text "CH 5-8" at 2120,-4910 h100 r90
  text "CH 1-4" at 1850,-6100 h100 r90
  text "Serial No" at 600,-6600 h100
Mechanical 1:
  lines w10: 0,-7000 0,-5800 50,-5800 50,-4500 50,-3200 0,-3200 0,3000 2600,3000 2600,-7000 0,-7000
